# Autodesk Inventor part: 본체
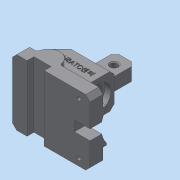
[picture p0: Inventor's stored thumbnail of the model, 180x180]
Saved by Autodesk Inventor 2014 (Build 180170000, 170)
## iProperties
Created: 2022-08
Part Number: 본체
Material: 일반
Document SubType Name: Modeling
Designer: dg
Density: 1 g/cm^3
Appearance: 기본값
Author: dg
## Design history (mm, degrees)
sketch "스케치1"
  geometry: L1 (0, 0)-(17, 0); L2 (17, 0)-(17, 8); L3 (17, 8)-(37, 8); L4 (37, 8)-(37, 0); L5 (37, 0)-(90, 0); L6 (90, 0)-(90, 15); L7 (0, 15)-(0, 0); L8 (90, 15)-(40, 15); L9 (14, 15)-(0, 15); L10 (18, 60)-(58, 60); L11 (58, 60)-(58, 19); L12 (58, 19)-(90, 19); L13 (90, 19)-(90, 15); L14 (0, 15)-(0, 42); L15 (0, 42)-(18, 60); A1 r 13 centre (27, 15) between (40, 15) and (14, 15); 1 further point
  constraints: 30 end point, 8 parallel, 2 horizontal alignment, 2 point on circle, 2 vertical, 1 centre point, 1 collinear, 1 horizontal, 1 midpoint, 1 perpendicular, 1 vertical alignment
  dimensions: "d2" = 20 distance of L2.end L3.end; "d3" = 27 distance from line of L7 point (27, 8); "d4" = 8 distance of L1.end L2.end; "d5" = 15 distance of L7.start L1.start; "d7" = 13 radius of A1; "d8" = 63 distance from line of L6 point (27, 8); "d9" = 15 distance of L5.end L6.end; "d10" = 45 distance between parallel lines of L9 L10; "d11" = 45 deg angle of L10 L15; "d12" = 18 horizontal distance of L14.end L10.start; "d13" = 32 distance of L11.end L12.end; "d14" = 4 distance between parallel lines of L8 L12
extrude "돌출1" new body sketch "스케치1" stored distance "d15" = 76; taper "d16" = 0 deg
extrude "돌출2" join sketch "스케치1" stored distance "d17" = 40; taper "d18" = 0 deg
node "작업 평면1"
sketch "스케치2"
  geometry: L1 (58, 60)-(18, 60) reference; L2 (29, 60)-(29, 90); L3 (29, 90)-(53, 90); L4 (53, 90)-(53, 60); L5 (58, 19)-(58, 60) reference; 1 further point
  constraints: 6 end point, 3 perpendicular, 2 point on line
  dimensions: "d19" = 30 distance of L2.start L2.end; "d20" = 24 distance of L2.end L3.end; "d21" = 5 distance between parallel lines of L5 L4
extrude "돌출3" join sketch "스케치2" stored distance "d22" = 15; taper "d23" = 0 deg
chamfer "모따기1" distance "d24" = 5; stored, may be unused: second distance "d25" = 2, angle "d26" = 45 deg
fillet "모깎기1" dims "d27" = 3
fillet "모깎기2" dims "d28" = 3
chamfer "모따기2" distance "d29" = 5; stored, may be unused: second distance "d30" = 2, angle "d31" = 45 deg
fillet "모깎기3" dims "d32" = 3
chamfer "모따기3" distance "d33" = 5; stored, may be unused: second distance "d34" = 2, angle "d35" = 45 deg
sketch "스케치3"
  geometry: L1 (53, -19)-(-13, -19) reference; 3 further points
  constraints: 1 midpoint, 1 vertical alignment
  dimensions: "d36" = 42 distance from line of L1 point (20, 23)
hole "구멍1" sketch "스케치3" at (20, 23) diameter "d37" = 20; stored, may be unused: countersink angle "d41" = 90 deg, drill point angle "d43" = 118 deg; dims "d38" = 6, "d39" = 29, "d40" = 7, "d42" = 8
sketch "스케치4"
  geometry: L1 (-34, 90)-(-48, 90) reference; L2 (-85, 0)-(-37, 0) reference; L3 (-58, 55)-(-13, 55) reference; L4 (-58, 55)-(-58, 19) reference; L5 (-58, 19)-(-90, 19) reference; L6 (-90, 19)-(-90, 15) reference; L7 (-42.716, 15)-(-90, 15) reference; L8 (0, 15)-(-11.284, 15) reference; L9 (0, 15)-(0, 42) reference; L10 (0, 42)-(-13, 55) reference; A1 r 3 centre (-42.716, 18) between (-42.716, 15) and (-39.769, 17.438) reference; A2 r 13 centre (-27, 15) between (-14.231, 17.437) and (-39.769, 17.438) reference; A3 r 3 centre (-11.284, 18) between (-14.231, 17.437) and (-11.284, 15) reference; 3 further points
  constraints: 1 midpoint, 1 vertical alignment
  dimensions: "d47" = 77 distance from line of L2 point (-41, 77)
hole "구멍2" sketch "스케치4" at (-41, 77) diameter "d48" = 8; stored, may be unused: countersink angle "d52" = 90 deg, drill point angle "d54" = 118 deg; dims "d49" = 6, "d50" = 29, "d51" = 7, "d53" = 8
chamfer "모따기5" distance "d55" = 1; stored, may be unused: second distance "d56" = 2, angle "d57" = 45 deg
sketch "스케치5"
  geometry: L1 (0, 4)-(-40, 4) reference; L2 (13, -15)-(-53, -15) reference; L3 (-26, -1.373)-(-26, -15); L4 (-14, -1.373)-(-14, -15); C1 r 14.5 at (-20, 27) reference; A1 r 29 centre (-20, 27) between (-37.664, 4) and (-26, -1.373); A2 r 29 centre (-20, 27) between (-14, -1.373) and (-2.336, 4); 1 further point
  constraints: 4 end point, 4 point on circle, 4 point on line, 2 centre point, 2 perpendicular, 1 coincident, 1 parallel
  dimensions: "d59" = 12 distance between parallel lines of L4 L3; "d60" = 29 radius of A1; "d61" = 29 radius of A2
extrude "돌출4" cut sketch "스케치5" distance "d62" = 18; taper "d63" = 0 deg
sketch "스케치6"
  geometry: L1 (0, 40)-(0, 58) reference; L2 (0, 40)-(47.284, 40) reference; L3 (47.284, 53)-(47.284, 40) reference; L4 (42.284, 58)-(47.284, 53) reference; L5 (0, 58)-(42.284, 58) reference; L6 (29.284, 2.336)-(29.284, 37.664) reference; L7 (15.284, 35)-(15.284, 5) reference; L8 (-42.716, 0)-(-42.716, -13) reference; 3 further points
  constraints: 1 vertical alignment
  dimensions: "d64" = 60 distance of point (34.284, 50) point (34.284, -10); "d66" = 8 distance from line of L5 point (34.284, 50); "d67" = 77 distance from line of L8 point (34.284, -10)
hole "구멍3" sketch "스케치6" at (34.284, 50), (34.284, -10) diameter "d68" = 4.5; stored, may be unused: countersink angle "d72" = 90 deg, drill point angle "d74" = 118 deg; dims "d69" = 6, "d70" = 8, "d71" = 4.4, "d73" = 8
fillet "모깎기4" dims "d75" = 3
chamfer "모따기6" distance "d76" = 1; stored, may be unused: second distance "d77" = 2, angle "d78" = 45 deg
sketch "스케치7"
  geometry: L1 (58, 22)-(58, 55) reference; L2 (58, 60)-(18, 60) reference; 2 further points
  constraints: 1 other
  dimensions: "d79" = 18 distance from line of L2 point (32, 42); "d80" = 26 distance from line of L1 point (32, 42)
feature "엠보싱1" sketch "스케치7" dims "d2" = 20, "d3" = 27, "d4" = 8, "d5" = 15, "d7" = 13, "d8" = 63, "d9" = 15, "d10" = 45, "d11" = 45 deg, "d12" = 18, "d13" = 32, "d14" = 4, "d81" = 0.5, "d82" = 0
node "솔리드1"
node "투영된 루프1"
node "투영된 루프2"
other parameters: "d6" = 26, "d58" = 58
